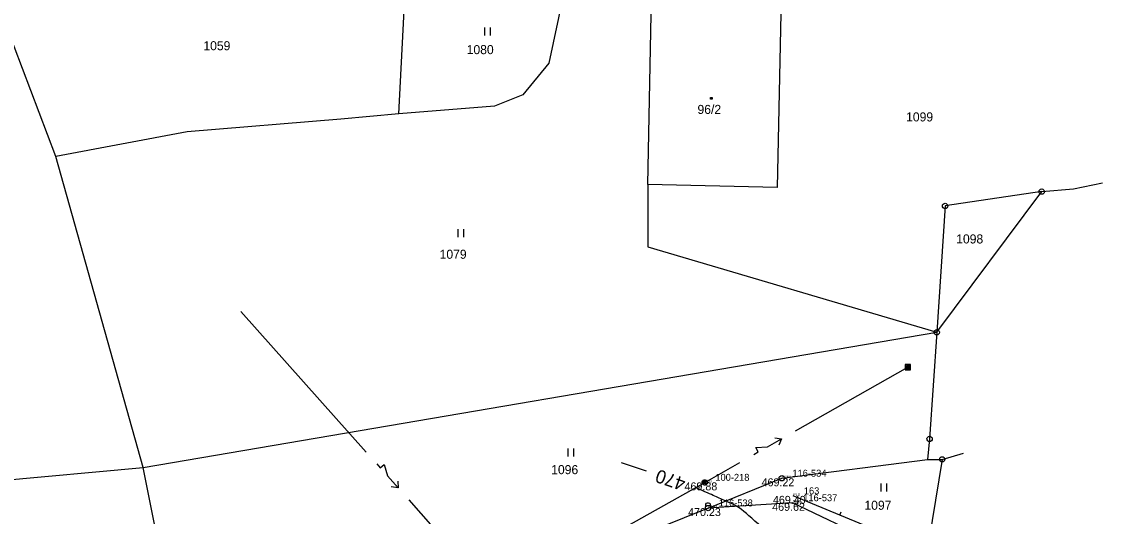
# Model space of a CAD drawing. Extents: x -604848 to -603227, y -1111879 to -1109838.
# Drawn here: x -603652.8 to -603450.2, y -1110217.6 to -1110124.8 of the extents above; entities that cross this region are included whole.
import ezdxf

# ---------------------------------------------------------------- set-up
doc = ezdxf.new("R2010")
doc.units = 0
for name, color, linetype in [('1', 7, 'Continuous'), ('12', 7, 'Continuous'), ('14', 7, 'Continuous'), ('15', 7, 'Continuous'), ('18', 7, 'Continuous'), ('19', 7, 'Continuous'), ('20', 7, 'Continuous'), ('23', 7, 'Continuous'), ('25', 7, 'Continuous'), ('26', 7, 'Continuous'), ('28', 7, 'Continuous'), ('4', 7, 'Continuous'), ('7', 7, 'Continuous'), ('Default', 7, 'Continuous')]:
    doc.layers.add(name, color=color, linetype=linetype)

# ---------------------------------------------------------------- blocks, each defined once
blk = doc.blocks.new('Z601')
at = {"layer": '26'}
for p, q in [((-0.5, 0.1), (-0.4, 0.3)), ((-0.5, -0.1), (-0.5, 0.1)), ((-0.4, 0.3), (-0.3, 0.4)), ((-0.3, 0.4), (-0.1, 0.5)), ((-0.3, 0.2), (-0.3, -0.2)), ((-0.1, 0.5), (0.1, 0.5)), ((-0.1, -0.3), (-0.1, 0.3)), ((-0.1, 0.3), (0.1, 0.3)), ((0.1, 0.5), (0.3, 0.4)), ((0.1, 0.3), (0.1, -0.3)), ((0.3, 0.4), (0.4, 0.3)), ((0.3, -0.2), (0.3, 0.2)), ((0.4, 0.3), (0.5, 0.1)), ((0.5, 0.1), (0.5, -0.1)), ((-0.4, -0.3), (-0.5, -0.1)), ((-0.3, -0.4), (-0.4, -0.3)), ((-0.3, -0.2), (-0.1, -0.3)), ((-0.1, -0.5), (-0.3, -0.4)), ((0.1, -0.5), (-0.1, -0.5)), ((0.1, -0.3), (0.3, -0.2)), ((0.3, -0.4), (0.1, -0.5)), ((0.4, -0.3), (0.3, -0.4)), ((0.5, -0.1), (0.4, -0.3))]:
    blk.add_line(p, q, dxfattribs=at)
blk = doc.blocks.new('Z602')
at = {"layer": '26'}
for p, q in [((0.5, 0.5), (-0.5, 0.5)), ((-0.5, 0.5), (-0.5, -0.5)), ((0.3, 0.3), (-0.3, 0.3)), ((-0.3, 0.3), (-0.3, -0.1)), ((0.1, 0.1), (-0.2, 0.1)), ((0.1, -0.1), (0.1, 0.1)), ((0.3, -0.3), (0.3, 0.3)), ((0.5, -0.5), (0.5, 0.5)), ((-0.5, -0.5), (-0.3, -0.3)), ((-0.5, -0.5), (0.5, -0.5)), ((-0.3, -0.1), (0.1, -0.1)), ((-0.3, -0.3), (0.3, -0.3))]:
    blk.add_line(p, q, dxfattribs=at)
blk = doc.blocks.new('Z105')
at = {"layer": '28'}
for radius in [0.5, 0.01]:
    blk.add_circle((0, 0), radius, dxfattribs=at)
blk = doc.blocks.new('Z3060')
at = {"layer": '23'}
for p, q in [((-0.5, 0), (-0.5, 1.5)), ((0.5, 1.5), (0.5, 0))]:
    blk.add_line(p, q, dxfattribs=at)
blk = doc.blocks.new('Z402')
at = {"layer": '25'}
for p, q in [((-0.1, 0.1), (0.2, 0.1)), ((-0.1, -0.2), (-0.1, 0.1)), ((0.2, 0.1), (0.2, -0.2)), ((0.2, -0.2), (-0.1, -0.2))]:
    blk.add_line(p, q, dxfattribs=at)
blk = doc.blocks.new('POINT_DISPLAY')
at = {"layer": 'Default'}
blk.add_line((0, 0), (0, 0), dxfattribs=at)
blk = doc.blocks.new('Z210')
at = {"layer": '4'}
blk.add_line((0, 0), (0, 0.7), dxfattribs=at)
blk = doc.blocks.new('Z660')
at = {"layer": '12'}
for p, q in [((-3, 0), (-2, 0)), ((-2, 0), (-2, 1)), ((-2, 1), (0, 0)), ((0, 0), (3, 0)), ((2, 0.8), (3, 0)), ((3, 0), (2, -0.8))]:
    blk.add_line(p, q, dxfattribs=at)
blk = doc.blocks.new('Z4')
at = {"layer": '4'}
for p, q in [((-0.4, 0.7), (-0.3, 0.9)), ((-0.4, 0.3), (-0.4, 0.7)), ((-0.3, 0.9), (-0.1, 1)), ((-0.1, 1), (0.1, 1)), ((0.1, 1), (0.3, 0.9)), ((0.3, 0.9), (0.4, 0.7)), ((0.4, 0.7), (0.4, 0.3))]:
    blk.add_line(p, q, dxfattribs=at)

msp = doc.modelspace()

# ---------------------------------------------------------------- linework, layer by layer
at = {"layer": '1'}
for p, q in [((-603646.37, -1110150.13), (-603661.5, -1110110.29)), ((-603582.11, -1110142.12), (-603580.73, -1110115.61)), ((-603550.69, -1110117.18), (-603553.98, -1110132.61)), ((-603535.42, -1110155.37), (-603534.68, -1110118)), ((-603510.4, -1110117.8), (-603511.16, -1110155.92)), ((-603553.98, -1110132.61), (-603558.85, -1110138.56)), ((-603558.85, -1110138.56), (-603564.18, -1110140.71)), ((-603564.18, -1110140.71), (-603582.11, -1110142.12)), ((-603592.98, -1110143.1), (-603621.78, -1110145.49)), ((-603582.11, -1110142.12), (-603592.98, -1110143.1)), ((-603621.78, -1110145.49), (-603646.37, -1110150.13)), ((-603630.01, -1110208.48), (-603646.37, -1110150.13)), ((-603511.16, -1110155.92), (-603535.42, -1110155.37)), ((-603535.42, -1110155.37), (-603535.42, -1110167.04)), ((-603455.67, -1110156.2), (-603450.23, -1110155.09)), ((-603481.28, -1110183.1), (-603461.61, -1110156.72)), ((-603461.61, -1110156.72), (-603479.72, -1110159.39)), ((-603461.61, -1110156.72), (-603455.67, -1110156.2)), ((-603479.72, -1110159.39), (-603481.28, -1110183.1)), ((-603535.42, -1110167.04), (-603481.28, -1110183.1)), ((-603630.01, -1110208.48), (-603481.28, -1110183.1)), ((-603481.28, -1110183.1), (-603482.62, -1110203.1)), ((-603482.62, -1110203.1), (-603482.99, -1110206.96)), ((-603480.26, -1110206.93), (-603476.28, -1110205.8)), ((-603748.02, -1110219.29), (-603630.01, -1110208.48)), ((-603624.32, -1110237.13), (-603630.01, -1110208.48)), ((-603510.33, -1110210.48), (-603482.99, -1110206.96)), ((-603482.99, -1110206.96), (-603480.26, -1110206.93)), ((-603480.26, -1110206.93), (-603482.81, -1110222.63)), ((-603524.13, -1110216.06), (-603510.33, -1110210.48)), ((-603524.13, -1110216.06), (-603537.93, -1110221.64)), ((-603508.3, -1110215.08), (-603524.13, -1110216.06)), ((-603484.18, -1110226.58), (-603508.3, -1110215.08))]:
    msp.add_line(p, q, dxfattribs=at)
at = {"layer": '12'}
for p, q in [((-603611.68, -1110179.2), (-603588.23, -1110205.56)), ((-603507.76, -1110201.6), (-603486.67, -1110189.63)), ((-603524.77, -1110211.25), (-603518.19, -1110207.52)), ((-603563.7, -1110233.14), (-603524.77, -1110211.25)), ((-603580.25, -1110214.53), (-603563.7, -1110233.14))]:
    msp.add_line(p, q, dxfattribs=at)
at = {"layer": '4'}
msp.add_line((-603485.58, -1110223.12), (-603508.19, -1110213.78), dxfattribs=at)
at = {"layer": '7'}
msp.add_line((-603535.65, -1110209.13), (-603540.34, -1110207.61), dxfattribs=at)
msp.add_open_spline([(-603511.97, -1110221.22), (-603514.93, -1110219.06), (-603517.5, -1110216.23), (-603520.84, -1110214.73), (-603522.72, -1110213.89), (-603524.6, -1110213.05), (-603526.47, -1110212.21)], degree=3, dxfattribs=at)

# ---------------------------------------------------------------- block references
at = {"layer": '12'}
for p, xscale, yscale, rotation in [((-603512.98, -1110204.56), 0.9999965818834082, 0.9999965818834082, 29.572796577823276), ((-603584.24, -1110210.04), 0.9999979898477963, 0.9999979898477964, -48.346652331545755)]:
    msp.add_blockref('Z660', p, dxfattribs=dict(at, xscale=xscale, yscale=yscale, rotation=rotation))
at = {"layer": '18'}
for p in [(-603510.33, -1110210.48), (-603524.77, -1110211.25), (-603508.19, -1110213.78), (-603524.13, -1110216.06), (-603508.3, -1110215.08)]:
    msp.add_blockref('POINT_DISPLAY', p, dxfattribs=at)
at = {"layer": '23'}
for p in [(-603565.49, -1110127.42), (-603570.45, -1110165.24), (-603549.84, -1110206.39), (-603491.21, -1110212.95)]:
    msp.add_blockref('Z3060', p, dxfattribs=at)
at = {"layer": '25'}
msp.add_blockref('Z402', (-603523.57, -1110139.15), dxfattribs=at)
at = {"layer": '26'}
for name, p in [('Z602', (-603486.67, -1110189.63)), ('Z601', (-603524.77, -1110211.25))]:
    msp.add_blockref(name, p, dxfattribs=at)
at = {"layer": '28'}
for p in [(-603461.61, -1110156.72), (-603479.72, -1110159.39), (-603481.28, -1110183.1), (-603482.62, -1110203.1), (-603480.26, -1110206.93), (-603510.33, -1110210.48), (-603524.13, -1110216.06)]:
    msp.add_blockref('Z105', p, dxfattribs=at)
at = {"layer": '4'}
msp.add_blockref('Z4', (-603524.13, -1110216.06), dxfattribs=at)
at = {"layer": '4', "xscale": 0.9999988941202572, "yscale": 0.9999988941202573, "rotation": -22.445599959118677}
msp.add_blockref('Z210', (-603499.44, -1110217.39), dxfattribs=at)

# ---------------------------------------------------------------- texts
at = {"layer": '14'}
for s, p in [('1059', (-603618.73, -1110130.2)), ('1080', (-603569.38, -1110130.93)), ('1099', (-603487.02, -1110143.55)), ('1098', (-603477.63, -1110166.44)), ('1079', (-603574.45, -1110169.31)), ('1096', (-603553.54, -1110209.71)), ('1097', (-603494.83, -1110216.39))]:
    msp.add_text(s, height=1.7, dxfattribs=at).set_placement(p)
at = {"layer": '15'}
msp.add_text('96/2', height=1.7, dxfattribs=at).set_placement((-603526.12, -1110142.15))
at = {"layer": '18'}
for s, p in [('SLB', (-603524.77, -1110211.25)), ('UMM', (-603510.33, -1110210.48)), ('DRK', (-603508.3, -1110215.08)), ('PLD', (-603508.19, -1110213.78)), ('UMM', (-603524.13, -1110216.06))]:
    msp.add_text(s, height=0.5, dxfattribs=at).set_placement(p)
at = {"layer": '19'}
for s, p in [('100-218', (-603522.77, -1110210.95)), ('116-534', (-603508.33, -1110210.18)), ('163', (-603506.19, -1110213.48)), ('116-538', (-603522.13, -1110215.76)), ('116-537', (-603506.3, -1110214.78))]:
    msp.add_text(s, height=1.3, dxfattribs=at).set_placement(p)
at = {"layer": '20'}
for s, p in [('469.22 ', (-603514.11, -1110211.98)), ('469.88 ', (-603528.55, -1110212.75)), ('469.40 ', (-603511.98, -1110215.28)), ('470.23 ', (-603527.88, -1110217.56)), ('469.62 ', (-603512.12, -1110216.58))]:
    msp.add_text(s, height=1.5, dxfattribs=at).set_placement(p)
at = {"layer": '7'}
msp.add_text('470', height=2.5, rotation=161.1, dxfattribs=at).set_placement((-603528.16, -1110210.54))

doc.saveas('drawing.dxf')
